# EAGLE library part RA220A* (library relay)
MICROWAVE RELAY FOR ATTENUATOR CIRCUIT NAiS Source: http://www.mew-europe.com/.. en_ds_61308_0000.pdf
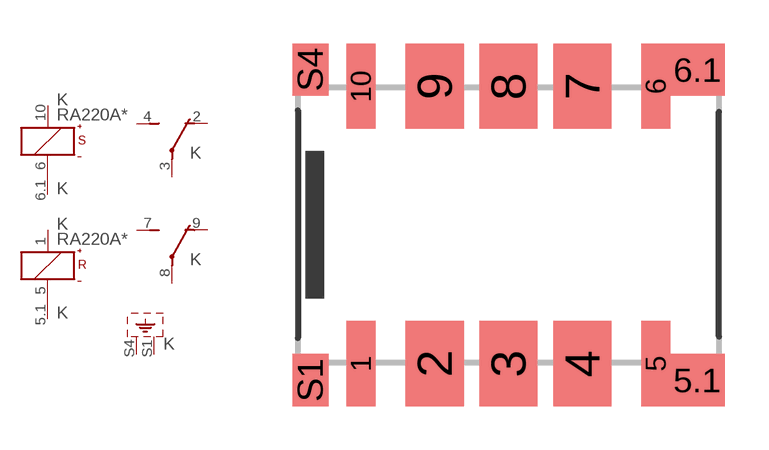
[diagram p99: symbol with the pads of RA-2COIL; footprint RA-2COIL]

Designator prefix K; gates S=K+-S R=K+-R 1=U 2=U SH=SHIELD-2 P5=K-PIN P6=K-PIN

## RA220A1H (OC_FARNELL: unknown; OC_NEWARK: unknown), RA220A03 (MPN: ARA220A03Z; OC_FARNELL: unknown; OC_NEWARK: 12N3559), RA220A4H (MPN: ARA220A4HZ; OC_FARNELL: unknown; OC_NEWARK: 12N3561), RA220A05 (MPN: ARA220A05; OC_FARNELL: unknown; OC_NEWARK: 15P8679), RA220A06 (OC_FARNELL: unknown; OC_NEWARK: unknown), RA220A09 (OC_FARNELL: unknown; OC_NEWARK: unknown), RA220A12 (MPN: ARA220A12Z; OC_FARNELL: unknown; OC_NEWARK: 12N3560), RA220A24 (OC_FARNELL: unknown; OC_NEWARK: unknown)  [RA-2COIL]
1  R:+  pas
2  1:O  pas
3  1:P  pas
4  1:S  pas
5  R:-  pas
5.1  P5:-  pas
6  S:-  pas
6.1  P6:-  pas
7  2:S  pas
8  2:P  pas
9  2:O  pas
10  S:+  pas
S1  SH:SH  pas
S4  SH:SH  pas

## Footprint RA-2COIL (pad centres in mm)
MICROWAVE RELAY FOR ATTENUATOR CIRCUIT NAiS Source: http://www.mew-europe.com/.. en_ds_61308_0000.pdf
smd 1 x 2.94: 1 -5.08,-4.78; 5 5.08,-4.78; 6 5.08,4.78; 10 -5.08,4.78
smd 2 x 2.94: 2 -2.54,-4.78; 3 0,-4.78; 4 2.54,-4.78; 7 2.54,4.78; 8 0,4.78; 9 -2.54,4.78
smd 1.9 x 1.8: 5.1 6.5,-5.35; 6.1 6.51,5.35
smd 1.25 x 1.8: S1 -6.82,-5.35; S4 -6.82,5.35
